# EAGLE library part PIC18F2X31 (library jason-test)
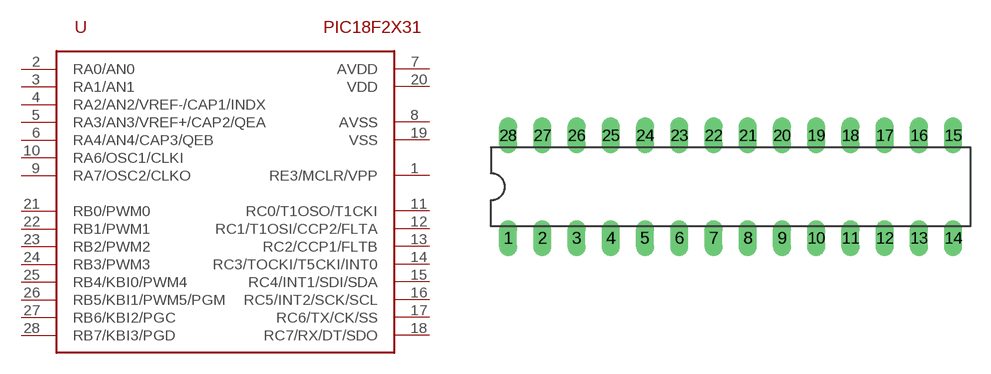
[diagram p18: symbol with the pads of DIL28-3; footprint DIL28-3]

Designator prefix -

## PIC18F2X31P  [DIL28-3]
1  RE3/MCLR/VPP  in
2  RA0/AN0
3  RA1/AN1
4  RA2/AN2/VREF-/CAP1/INDX
5  RA3/AN3/VREF+/CAP2/QEA
6  RA4/AN4/CAP3/QEB
7  AVDD  pwr
8  AVSS  pwr
9  RA7/OSC2/CLKO
10  RA6/OSC1/CLKI
11  RC0/T1OSO/T1CKI
12  RC1/T1OSI/CCP2/FLTA
13  RC2/CCP1/FLTB
14  RC3/TOCKI/T5CKI/INT0
15  RC4/INT1/SDI/SDA
16  RC5/INT2/SCK/SCL
17  RC6/TX/CK/SS
18  RC7/RX/DT/SDO
19  VSS  pwr
20  VDD  pwr
21  RB0/PWM0
22  RB1/PWM1
23  RB2/PWM2
24  RB3/PWM3
25  RB4/KBI0/PWM4
26  RB5/KBI1/PWM5/PGM
27  RB6/KBI2/PGC
28  RB7/KBI3/PGD

## Footprint DIL28-3 (pad centres in mm)
Dual In Line Package Small
drill 0.813 long: 1 -16.51,-3.81; 2 -13.97,-3.81; 3 -11.43,-3.81; 4 -8.89,-3.81; 5 -6.35,-3.81; 6 -3.81,-3.81; 7 -1.27,-3.81; 8 1.27,-3.81; 9 3.81,-3.81; 10 6.35,-3.81; 11 8.89,-3.81; 12 11.43,-3.81; 13 13.97,-3.81; 14 16.51,-3.81; 15 16.51,3.81; 16 13.97,3.81; 17 11.43,3.81; 18 8.89,3.81; 19 6.35,3.81; 20 3.81,3.81; 21 1.27,3.81; 22 -1.27,3.81; 23 -3.81,3.81; 24 -6.35,3.81; 25 -8.89,3.81; 26 -11.43,3.81; 27 -13.97,3.81; 28 -16.51,3.81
